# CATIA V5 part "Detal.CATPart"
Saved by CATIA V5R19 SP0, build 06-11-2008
Part number: Detal
Bounding box of the stored display mesh (mm): x -39.842 to 40, y -39.842 to 39.842, z 0 to 127.969
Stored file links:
  G:\Catia\CD\Ustawienia\Ustawienia\Detal.CATPart
  C:\Program Files\Dassault Systemes\B12\intel_a\reffiles\standard\MetricThinPitch.txt
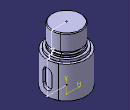
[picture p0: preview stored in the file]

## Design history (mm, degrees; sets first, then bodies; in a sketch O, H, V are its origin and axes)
Set1
  Plane1: type Offset, Offset 40, RefPlane yz-plane
Body1 "detal" (main body)
  Sketch1 on zx-plane, origin (0, 0, 0), H (-1, 0, 0), V (0, 0, 1)
    point P1 (-26, 94.9687)
    point P2 (-26, 88.9687)
    point P3 (-35, 85.9687)
    point P4 (-35, 80.9687)
    point P5 (0, 15.9687)
    line L1 (-30, 126.5545) -> (-30, 95.7463)
    line L2 (-30, 95.7463) -> (-27.6184, 95.2833)
    line L3 (-28, 88.9687) -> (-30, 88.9687)
    line L4 (-30, 88.9687) -> (-30, 86.2687)
    line L5 (-30.3, 85.9687) -> (-35, 85.9687)
    line L6 (-35.3, 80.9687) -> (-40, 80.9687)
    line L7 (-40, 80.9687) -> (-40, 15.9687)
    line L8 (-26, 93.3201) -> (-26, 90.9687)
    line L9 (-35, 85.9687) -> (-35, 81.2687)
    line L10 (-40, 15.9687) -> (0, 15.9687)
    axis line L11 (0, 15.9687) -> (0, 139.8494)
    point P11 (0, 15.9687)
    arc A1 centre (-28, 93.3201) radius 2 from (-27.6184, 95.2833) to (-26, 93.3201) cw
    arc A2 centre (-28, 90.9687) radius 2 from (-26, 90.9687) to (-28, 88.9687) cw
    arc A3 centre (-30.3, 86.2687) radius 0.3 from (-30, 86.2687) to (-30.3, 85.9687) cw
    arc A4 centre (-35.3, 81.2687) radius 0.3 from (-35, 81.2687) to (-35.3, 80.9687) cw
    line L12 (-30, 126.5545) -> (-28.5858, 127.9687)
    line L13 (-28.5858, 127.9687) -> (0, 127.9687)
    point P26 (0, 127.9687)
    distance L5 L3 = 3
    distance L8 L1 = 4
    angle L2 L8 = 101
    angle L7 L6 = 90
    length L7 = 65
    distance P1 P2 = 6
    radius A1 = 2
    radius A2 = 2
    radius A3 = 0.3
    distance P3 P4 = 5
    radius A4 = 0.3
    angle L13 L12 = 45
    distance L7 L11 = 40
    distance L10 L13 = 112
    length L12 = 2
    distance L9 L11 = 35
    distance L1 L11 = 30
    vertical: L4 V, L1 V, L11 V
    horizontal: L3 H, L10 H, L13 H
    coincidence: P11 V, L1 L4, L2 P1, L8 P1, L8 P2, L3 P2, L9 P4, L6 P4, P26 L11, P5 P11
    tangency: A1 L2, A1 L8, A2 L8, A2 L3, A3 L4, A3 L5, A4 L9, A4 L6
  Shaft1: profile Sketch1, axis edge of Sketch1, angle 360
  Sketch2 on Plane1, origin (40, 0, 0), H (0, 1, 0), V (0, 0, 1)
    point P1 (5, 72.2332)
    point P2 (-5, 72.2332)
    construction line L1 (0, 57.9982) -> (0, 35.9982)
    line L2 (9, 57.9982) -> (9, 35.9982)
    line L3 (-9, 35.9982) -> (-9, 57.9982)
    arc A1 centre (0, 35.9982) radius 9 from (9, 35.9982) to (-9, 35.9982) cw
    arc A2 centre (0, 57.9982) radius 9 from (-9, 57.9982) to (9, 57.9982) cw
    reference projected line E1 (0, 82.4524) -> (0, 52.4524) from Sketch1.L9
    distance A2 A1 = 40
    distance L2 L3 = 18
    vertical: L1 V
    tangency: A1 L2, A2 L2, A1 L3, A2 L3
    coincidence: L1 E1
  Pocket1: profile Sketch2, direction (-1, 0, 0), length 6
